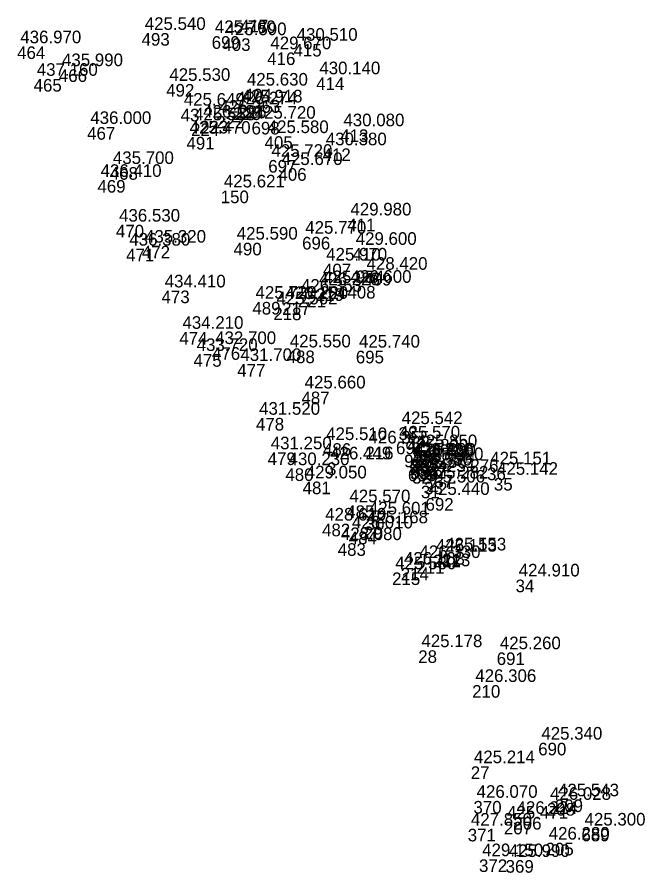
# Model space of a CAD drawing. Extents: x -874038 to -859694, y -1059487 to -1049069.
# Drawn here: x -860223.6 to -860163.9, y -1059080.6 to -1058999.2 of the extents above; entities that cross this region are included whole.
import ezdxf

# ---------------------------------------------------------------- set-up
doc = ezdxf.new("R2010")
doc.units = 0
doc.layers.add('Vrstva 60', color=7, linetype='Continuous')
doc.layers.add('Vrstva 61', color=7, linetype='Continuous')

msp = doc.modelspace()

# ---------------------------------------------------------------- linework, layer by layer
at = {"layer": 'Vrstva 60'}
for p, q in [((-860202.39, -1058999.44), (-860202.39, -1058999.44)), ((-860211.77, -1059000.7), (-860211.77, -1059000.7)), ((-860205.1, -1059001), (-860205.1, -1059001)), ((-860204.08, -1059001.2), (-860204.08, -1059001.2)), ((-860197.32, -1059001.73), (-860197.32, -1059001.73)), ((-860223.61, -1059001.97), (-860223.61, -1059001.97)), ((-860199.82, -1059002.54), (-860199.82, -1059002.54)), ((-860219.64, -1059004.15), (-860219.64, -1059004.15)), ((-860222.04, -1059005.07), (-860222.04, -1059005.07)), ((-860195.16, -1059004.92), (-860195.16, -1059004.92)), ((-860209.43, -1059005.55), (-860209.43, -1059005.55)), ((-860202.05, -1059006), (-860202.05, -1059006)), ((-860202.562, -1059007.601), (-860202.562, -1059007.601)), ((-860208.054, -1059007.909), (-860208.054, -1059007.909)), ((-860203.08, -1059007.776), (-860203.08, -1059007.776)), ((-860206.214, -1059009.054), (-860206.214, -1059009.054)), ((-860204.674, -1059008.583), (-860204.674, -1059008.583)), ((-860201.31, -1059009.15), (-860201.31, -1059009.15)), ((-860216.95, -1059009.65), (-860216.95, -1059009.65)), ((-860207.064, -1059009.306), (-860207.064, -1059009.306)), ((-860192.87, -1059009.87), (-860192.87, -1059009.87)), ((-860207.5, -1059010.58), (-860207.5, -1059010.58)), ((-860200.07, -1059010.52), (-860200.07, -1059010.52)), ((-860194.55, -1059011.68), (-860194.55, -1059011.68)), ((-860199.72, -1059012.78), (-860199.72, -1059012.78)), ((-860214.8, -1059013.46), (-860214.8, -1059013.46)), ((-860198.75, -1059013.56), (-860198.75, -1059013.56)), ((-860215.97, -1059014.69), (-860215.97, -1059014.69)), ((-860204.242, -1059015.693), (-860204.242, -1059015.693)), ((-860214.21, -1059018.95), (-860214.21, -1059018.95)), ((-860192.2, -1059018.36), (-860192.2, -1059018.36)), ((-860196.5, -1059020.1), (-860196.5, -1059020.1)), ((-860213.24, -1059021.23), (-860213.24, -1059021.23)), ((-860211.74, -1059020.95), (-860211.74, -1059020.95)), ((-860203.02, -1059020.66), (-860203.02, -1059020.66)), ((-860191.7, -1059021.16), (-860191.7, -1059021.16)), ((-860194.51, -1059022.65), (-860194.51, -1059022.65)), ((-860190.67, -1059023.53), (-860190.67, -1059023.53)), ((-860209.87, -1059025.21), (-860209.87, -1059025.21)), ((-860195.196, -1059025.001), (-860195.196, -1059025.001)), ((-860194.803, -1059024.801), (-860194.803, -1059024.801)), ((-860192.19, -1059024.77), (-860192.19, -1059024.77)), ((-860201.23, -1059026.29), (-860201.23, -1059026.29)), ((-860198.4, -1059026.322), (-860198.4, -1059026.322)), ((-860196.904, -1059025.619), (-860196.904, -1059025.619)), ((-860199.238, -1059026.825), (-860199.238, -1059026.825)), ((-860208.18, -1059029.15), (-860208.18, -1059029.15)), ((-860205.07, -1059030.6), (-860205.07, -1059030.6)), ((-860197.97, -1059030.92), (-860197.97, -1059030.92)), ((-860191.39, -1059030.94), (-860191.39, -1059030.94)), ((-860206.83, -1059031.26), (-860206.83, -1059031.26)), ((-860202.67, -1059032.21), (-860202.67, -1059032.21)), ((-860196.56, -1059034.83), (-860196.56, -1059034.83)), ((-860200.89, -1059037.33), (-860200.89, -1059037.33)), ((-860187.331, -1059038.221), (-860187.331, -1059038.221)), ((-860194.51, -1059039.74), (-860194.51, -1059039.74)), ((-860190.48, -1059040.064), (-860190.48, -1059040.064)), ((-860187.57, -1059039.59), (-860187.57, -1059039.59)), ((-860199.78, -1059040.62), (-860199.78, -1059040.62)), ((-860186.79, -1059040.83), (-860186.79, -1059040.83)), ((-860185.94, -1059040.42), (-860185.94, -1059040.42)), ((-860194.131, -1059041.576), (-860194.131, -1059041.576)), ((-860186.281, -1059041.354), (-860186.281, -1059041.354)), ((-860186.269, -1059041.206), (-860186.269, -1059041.206)), ((-860186.08, -1059041.23), (-860186.08, -1059041.23)), ((-860185.35, -1059041.65), (-860185.35, -1059041.65)), ((-860198.09, -1059042.13), (-860198.09, -1059042.13)), ((-860186.43, -1059042.16), (-860186.43, -1059042.16)), ((-860186.24, -1059042), (-860186.24, -1059042)), ((-860186.192, -1059041.935), (-860186.192, -1059041.935)), ((-860186.036, -1059042.386), (-860186.036, -1059042.386)), ((-860178.904, -1059042.057), (-860178.904, -1059042.057)), ((-860196.45, -1059043.39), (-860196.45, -1059043.39)), ((-860184.884, -1059043.4), (-860184.884, -1059043.4)), ((-860183.917, -1059042.771), (-860183.917, -1059042.771)), ((-860178.256, -1059043.047), (-860178.256, -1059043.047)), ((-860185.195, -1059043.783), (-860185.195, -1059043.783)), ((-860184.76, -1059044.96), (-860184.76, -1059044.96)), ((-860192.3, -1059045.66), (-860192.3, -1059045.66)), ((-860194.6, -1059047.4), (-860194.6, -1059047.4)), ((-860190.447, -1059046.819), (-860190.447, -1059046.819)), ((-860192.06, -1059048.15), (-860192.06, -1059048.15)), ((-860190.626, -1059047.663), (-860190.626, -1059047.663)), ((-860193.11, -1059049.26), (-860193.11, -1059049.26)), ((-860184.071, -1059050.359), (-860184.071, -1059050.359)), ((-860183.181, -1059050.245), (-860183.181, -1059050.245)), ((-860185.631, -1059050.966), (-860185.631, -1059050.966)), ((-860187.939, -1059052.035), (-860187.939, -1059052.035)), ((-860187.114, -1059051.598), (-860187.114, -1059051.598)), ((-860176.194, -1059052.72), (-860176.194, -1059052.72)), ((-860185.451, -1059059.452), (-860185.451, -1059059.452)), ((-860177.99, -1059059.65), (-860177.99, -1059059.65)), ((-860180.323, -1059062.762), (-860180.323, -1059062.762)), ((-860174.04, -1059068.25), (-860174.04, -1059068.25)), ((-860180.455, -1059070.495), (-860180.455, -1059070.495)), ((-860180.2, -1059073.79), (-860180.2, -1059073.79)), ((-860173.213, -1059073.986), (-860173.213, -1059073.986)), ((-860172.457, -1059073.648), (-860172.457, -1059073.648)), ((-860177.302, -1059075.77), (-860177.302, -1059075.77)), ((-860176.399, -1059075.32), (-860176.399, -1059075.32)), ((-860180.74, -1059076.44), (-860180.74, -1059076.44)), ((-860169.93, -1059076.43), (-860169.93, -1059076.43)), ((-860173.341, -1059077.771), (-860173.341, -1059077.771)), ((-860179.67, -1059079.35), (-860179.67, -1059079.35)), ((-860177.14, -1059079.42), (-860177.14, -1059079.42))]:
    msp.add_line(p, q, dxfattribs=at)

# ---------------------------------------------------------------- texts
for s, p in [('417', (-860202.39, -1059000.64)), ('493', (-860211.77, -1059001.9)), ('699', (-860205.1, -1059002.2)), ('403', (-860204.08, -1059002.4)), ('415', (-860197.32, -1059002.93)), ('464', (-860223.61, -1059003.17)), ('416', (-860199.82, -1059003.74)), ('466', (-860219.64, -1059005.35)), ('465', (-860222.04, -1059006.27)), ('414', (-860195.16, -1059006.12)), ('492', (-860209.43, -1059006.75)), ('404', (-860202.05, -1059007.2)), ('226', (-860202.562, -1059008.801)), ('43', (-860208.054, -1059009.109)), ('225', (-860203.08, -1059008.976)), ('223', (-860206.214, -1059010.254)), ('222', (-860204.674, -1059009.783)), ('698', (-860201.31, -1059010.35)), ('467', (-860216.95, -1059010.85)), ('224', (-860207.064, -1059010.506)), ('413', (-860192.87, -1059011.07)), ('491', (-860207.5, -1059011.78)), ('405', (-860200.07, -1059011.72)), ('412', (-860194.55, -1059012.88)), ('697', (-860199.72, -1059013.98)), ('468', (-860214.8, -1059014.66)), ('406', (-860198.75, -1059014.76)), ('469', (-860215.97, -1059015.89)), ('150', (-860204.242, -1059016.893)), ('470', (-860214.21, -1059020.15)), ('411', (-860192.2, -1059019.56)), ('490', (-860203.02, -1059021.86)), ('696', (-860196.5, -1059021.3)), ('471', (-860213.24, -1059022.43)), ('472', (-860211.74, -1059022.15)), ('410', (-860191.7, -1059022.36)), ('407', (-860194.51, -1059023.85)), ('409', (-860190.67, -1059024.73)), ('473', (-860209.87, -1059026.41)), ('219', (-860195.196, -1059026.201)), ('220', (-860194.803, -1059026.001)), ('408', (-860192.19, -1059025.97)), ('489', (-860201.23, -1059027.49)), ('217', (-860198.4, -1059027.522)), ('221', (-860196.904, -1059026.819)), ('218', (-860199.238, -1059028.025)), ('474', (-860208.18, -1059030.35)), ('476', (-860205.07, -1059031.8)), ('488', (-860197.97, -1059032.12)), ('695', (-860191.39, -1059032.14)), ('475', (-860206.83, -1059032.46)), ('477', (-860202.67, -1059033.41)), ('487', (-860196.56, -1059036.03)), ('478', (-860200.89, -1059038.53)), ('38', (-860187.331, -1059039.421)), ('486', (-860194.51, -1059040.94)), ('216', (-860190.48, -1059041.264)), ('694', (-860187.57, -1059040.79)), ('479', (-860199.78, -1059041.82)), ('935', (-860186.79, -1059042.03)), ('936', (-860185.94, -1059041.62)), ('3', (-860194.131, -1059042.776)), ('42', (-860186.269, -1059042.406)), ('2', (-860186.281, -1059042.554)), ('938', (-860186.08, -1059042.43)), ('937', (-860185.35, -1059042.85)), ('480', (-860198.09, -1059043.33)), ('693', (-860186.43, -1059043.36)), ('934', (-860186.24, -1059043.2)), ('856', (-860186.192, -1059043.135)), ('32', (-860186.036, -1059043.586)), ('36', (-860178.904, -1059043.257)), ('481', (-860196.45, -1059044.59)), ('33', (-860184.884, -1059044.6)), ('37', (-860183.917, -1059043.971)), ('35', (-860178.256, -1059044.247)), ('31', (-860185.195, -1059044.983)), ('692', (-860184.76, -1059046.16)), ('485', (-860192.3, -1059046.86)), ('482', (-860194.6, -1059048.6)), ('30', (-860190.447, -1059048.019)), ('484', (-860192.06, -1059049.35)), ('29', (-860190.626, -1059048.863)), ('483', (-860193.11, -1059050.46)), ('212', (-860184.071, -1059051.559)), ('213', (-860183.181, -1059051.445)), ('214', (-860187.114, -1059052.798)), ('211', (-860185.631, -1059052.166)), ('215', (-860187.939, -1059053.235)), ('34', (-860176.194, -1059053.92)), ('28', (-860185.451, -1059060.652)), ('691', (-860177.99, -1059060.85)), ('210', (-860180.323, -1059063.962)), ('690', (-860174.04, -1059069.45)), ('27', (-860180.455, -1059071.695)), ('370', (-860180.2, -1059074.99)), ('208', (-860173.213, -1059075.186)), ('209', (-860172.457, -1059074.848)), ('207', (-860177.302, -1059076.97)), ('206', (-860176.399, -1059076.52)), ('371', (-860180.74, -1059077.64)), ('689', (-860169.93, -1059077.63)), ('205', (-860173.341, -1059078.971)), ('372', (-860179.67, -1059080.55)), ('369', (-860177.14, -1059080.62))]:
    msp.add_text(s, height=1.2, dxfattribs=at).set_placement(p)
at = {"layer": 'Vrstva 61'}
for s, p in [('425.540', (-860211.47, -1059000.4)), ('425.760', (-860204.8, -1059000.7)), ('425.590', (-860203.78, -1059000.9)), ('430.510', (-860197.02, -1059001.43)), ('436.970', (-860223.31, -1059001.67)), ('429.670', (-860199.52, -1059002.24)), ('435.990', (-860219.34, -1059003.85)), ('430.140', (-860194.86, -1059004.62)), ('437.160', (-860221.74, -1059004.77)), ('425.530', (-860209.13, -1059005.25)), ('425.630', (-860201.75, -1059005.7)), ('425.649', (-860207.754, -1059007.609)), ('426.274', (-860202.78, -1059007.476)), ('425.918', (-860202.262, -1059007.301)), ('426.191', (-860205.914, -1059008.754)), ('426.363', (-860204.374, -1059008.283)), ('436.000', (-860216.65, -1059009.35)), ('425.558', (-860206.764, -1059009.006)), ('425.720', (-860201.01, -1059008.85)), ('430.080', (-860192.57, -1059009.57)), ('425.470', (-860207.2, -1059010.28)), ('425.580', (-860199.77, -1059010.22)), ('430.380', (-860194.25, -1059011.38)), ('425.720', (-860199.42, -1059012.48)), ('435.700', (-860214.5, -1059013.16)), ('425.670', (-860198.45, -1059013.26)), ('436.410', (-860215.67, -1059014.39)), ('425.621', (-860203.942, -1059015.393)), ('429.980', (-860191.9, -1059018.06)), ('436.530', (-860213.91, -1059018.65)), ('425.770', (-860196.2, -1059019.8)), ('436.380', (-860212.94, -1059020.93)), ('435.320', (-860211.44, -1059020.65)), ('425.590', (-860202.72, -1059020.36)), ('429.600', (-860191.4, -1059020.86)), ('425.970', (-860194.21, -1059022.35)), ('428.420', (-860190.37, -1059023.23)), ('434.410', (-860209.57, -1059024.91)), ('426.223', (-860194.896, -1059024.701)), ('425.954', (-860194.503, -1059024.501)), ('426.600', (-860191.89, -1059024.47)), ('426.353', (-860196.604, -1059025.319)), ('425.720', (-860200.93, -1059025.99)), ('425.562', (-860198.938, -1059026.525)), ('426.154', (-860198.1, -1059026.022)), ('434.210', (-860207.88, -1059028.85)), ('432.700', (-860204.77, -1059030.3)), ('425.550', (-860197.67, -1059030.62)), ('425.740', (-860191.09, -1059030.64)), ('433.720', (-860206.53, -1059030.96)), ('431.700', (-860202.37, -1059031.91)), ('425.660', (-860196.26, -1059034.53)), ('431.520', (-860200.59, -1059037.03)), ('425.542', (-860187.031, -1059037.921)), ('425.510', (-860194.21, -1059039.44)), ('426.355', (-860190.18, -1059039.764)), ('425.570', (-860187.27, -1059039.29)), ('431.250', (-860199.48, -1059040.32)), ('425.820', (-860186.49, -1059040.53)), ('425.850', (-860185.64, -1059040.12)), ('426.449', (-860193.831, -1059041.276)), ('426.420', (-860185.981, -1059041.054)), ('428.256', (-860185.969, -1059040.906)), ('425.890', (-860185.78, -1059040.93)), ('425.820', (-860185.05, -1059041.35)), ('430.230', (-860197.79, -1059041.83)), ('425.550', (-860186.13, -1059041.86)), ('425.830', (-860185.94, -1059041.7)), ('425.839', (-860185.892, -1059041.635)), ('425.551', (-860185.736, -1059042.086)), ('425.151', (-860178.604, -1059041.757)), ('425.276', (-860183.617, -1059042.471)), ('425.142', (-860177.956, -1059042.747)), ('429.050', (-860196.15, -1059043.09)), ('425.506', (-860184.895, -1059043.483)), ('425.282', (-860184.584, -1059043.1)), ('425.440', (-860184.46, -1059044.66)), ('425.570', (-860192, -1059045.36)), ('428.610', (-860194.3, -1059047.1)), ('425.601', (-860190.147, -1059046.519)), ('426.010', (-860191.76, -1059047.85)), ('425.168', (-860190.326, -1059047.363)), ('428.080', (-860192.81, -1059048.96)), ('426.113', (-860183.771, -1059050.059)), ('425.553', (-860182.881, -1059049.945)), ('426.330', (-860185.331, -1059050.666)), ('425.580', (-860187.639, -1059051.735)), ('426.163', (-860186.814, -1059051.298)), ('424.910', (-860175.894, -1059052.42)), ('425.178', (-860185.151, -1059059.152)), ('425.260', (-860177.69, -1059059.35)), ('426.306', (-860180.023, -1059062.462)), ('425.340', (-860173.74, -1059067.95)), ('425.214', (-860180.155, -1059070.195)), ('426.070', (-860179.9, -1059073.49)), ('426.028', (-860172.913, -1059073.686)), ('425.543', (-860172.157, -1059073.348)), ('425.471', (-860177.002, -1059075.47)), ('426.224', (-860176.099, -1059075.02)), ('427.850', (-860180.44, -1059076.14)), ('425.300', (-860169.63, -1059076.13)), ('426.280', (-860173.041, -1059077.471)), ('429.150', (-860179.37, -1059079.05)), ('425.990', (-860176.84, -1059079.12))]:
    msp.add_text(s, height=1.2, dxfattribs=at).set_placement(p)

doc.saveas('drawing.dxf')
